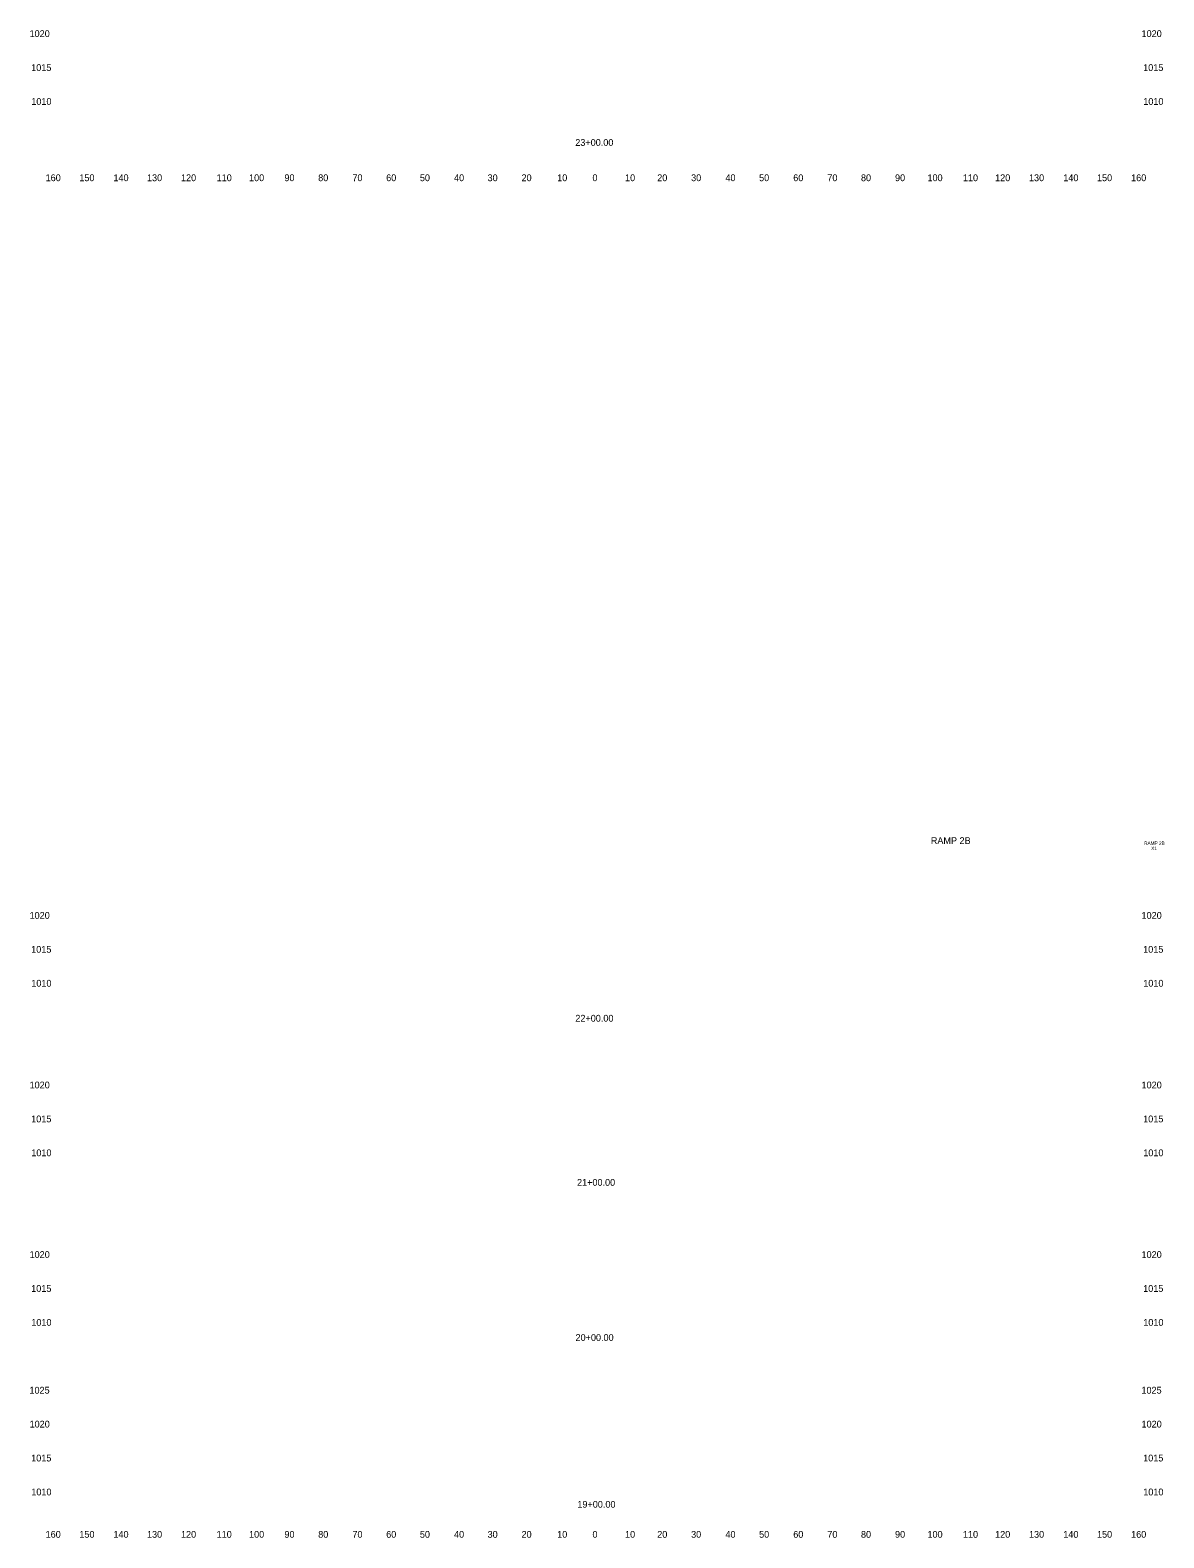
# Model space of a CAD drawing. Extents: x 4994 to 6358, y 4997 to 8804.
# Drawn here: x 4993.5 to 5327.7, y 4997.5 to 5442 of the extents above; entities that cross this region are included whole.
import ezdxf

# ---------------------------------------------------------------- set-up
doc = ezdxf.new("R2010")
doc.units = 0
for name, color, linetype in [('RD_SHT_ID', 7, 'Continuous'), ('RD_XS_TX_Offset', 7, 'Continuous'), ('RD_XS_TX_Station', 7, 'Continuous')]:
    doc.layers.add(name, color=color, linetype=linetype)

msp = doc.modelspace()

# ---------------------------------------------------------------- texts
at = {"layer": 'RD_SHT_ID'}
for s, height, p in [('RAMP 2B', 2, (5259.05, 5202.06)), ('RAMP 2B', 1, (5321.94, 5201.8)), ('X1', 1, (5324.02, 5200.3))]:
    msp.add_text(s, height=height, dxfattribs=at).set_placement(p)
at = {"layer": 'RD_XS_TX_Offset'}
for s, p in [('1020', (4993.37, 5440)), ('1020', (5321.17, 5440)), ('1015', (4993.85, 5430)), ('1015', (5321.65, 5430)), ('1010', (4993.88, 5420)), ('1010', (5321.68, 5420)), ('160', (4998.1, 5397.5)), ('150', (5008.04, 5397.5)), ('140', (5018.1, 5397.5)), ('130', (5027.99, 5397.5)), ('120', (5038.01, 5397.5)), ('110', (5048.51, 5397.5)), ('100', (5058.07, 5397.5)), ('90', (5068.5, 5397.5)), ('80', (5078.46, 5397.5)), ('70', (5088.54, 5397.5)), ('60', (5098.5, 5397.5)), ('50', (5108.43, 5397.5)), ('40', (5118.5, 5397.5)), ('30', (5128.39, 5397.5)), ('20', (5138.4, 5397.5)), ('10', (5148.91, 5397.5)), ('0', (5159.3, 5397.5)), ('0', (5159.3, 5397.5)), ('10', (5168.91, 5397.5)), ('20', (5178.4, 5397.5)), ('30', (5188.39, 5397.5)), ('40', (5198.5, 5397.5)), ('50', (5208.43, 5397.5)), ('60', (5218.5, 5397.5)), ('70', (5228.54, 5397.5)), ('80', (5238.46, 5397.5)), ('90', (5248.5, 5397.5)), ('100', (5258.07, 5397.5)), ('110', (5268.51, 5397.5)), ('120', (5278.01, 5397.5)), ('130', (5287.99, 5397.5)), ('140', (5298.1, 5397.5)), ('150', (5308.04, 5397.5)), ('160', (5318.1, 5397.5)), ('1020', (4993.37, 5180)), ('1020', (5321.17, 5180)), ('1015', (4993.85, 5170)), ('1015', (5321.65, 5170)), ('1010', (4993.88, 5160)), ('1010', (5321.68, 5160)), ('1020', (4993.37, 5130)), ('1020', (5321.17, 5130)), ('1015', (4993.85, 5120)), ('1015', (5321.65, 5120)), ('1010', (4993.88, 5110)), ('1010', (5321.68, 5110)), ('1020', (4993.37, 5080)), ('1020', (5321.17, 5080)), ('1015', (4993.85, 5070)), ('1015', (5321.65, 5070)), ('1010', (4993.88, 5060)), ('1010', (5321.68, 5060)), ('1025', (4993.34, 5040)), ('1025', (5321.14, 5040)), ('1020', (4993.37, 5030)), ('1020', (5321.17, 5030)), ('1015', (4993.85, 5020)), ('1015', (5321.65, 5020)), ('1010', (4993.88, 5010)), ('1010', (5321.68, 5010)), ('160', (4998.1, 4997.5)), ('150', (5008.04, 4997.5)), ('140', (5018.1, 4997.5)), ('130', (5027.99, 4997.5)), ('120', (5038.01, 4997.5)), ('110', (5048.51, 4997.5)), ('100', (5058.07, 4997.5)), ('90', (5068.5, 4997.5)), ('80', (5078.46, 4997.5)), ('70', (5088.54, 4997.5)), ('60', (5098.5, 4997.5)), ('50', (5108.43, 4997.5)), ('40', (5118.5, 4997.5)), ('30', (5128.39, 4997.5)), ('20', (5138.4, 4997.5)), ('10', (5148.91, 4997.5)), ('0', (5159.3, 4997.5)), ('0', (5159.3, 4997.5)), ('10', (5168.91, 4997.5)), ('20', (5178.4, 4997.5)), ('30', (5188.39, 4997.5)), ('40', (5198.5, 4997.5)), ('50', (5208.43, 4997.5)), ('60', (5218.5, 4997.5)), ('70', (5228.54, 4997.5)), ('80', (5238.46, 4997.5)), ('90', (5248.5, 4997.5)), ('100', (5258.07, 4997.5)), ('110', (5268.51, 4997.5)), ('120', (5278.01, 4997.5)), ('130', (5287.99, 4997.5)), ('140', (5298.1, 4997.5)), ('150', (5308.04, 4997.5)), ('160', (5318.1, 4997.5))]:
    msp.add_text(s, height=2, dxfattribs=at).set_placement(p)
at = {"layer": 'RD_XS_TX_Station'}
for s, p in [('23+00.00', (5154.24, 5407.91)), ('22+00.00', (5154.26, 5149.68)), ('21+00.00', (5154.76, 5101.28)), ('20+00.00', (5154.32, 5055.54)), ('19+00.00', (5154.86, 5006.36))]:
    msp.add_text(s, height=2, dxfattribs=at).set_placement(p)

doc.saveas('drawing.dxf')
